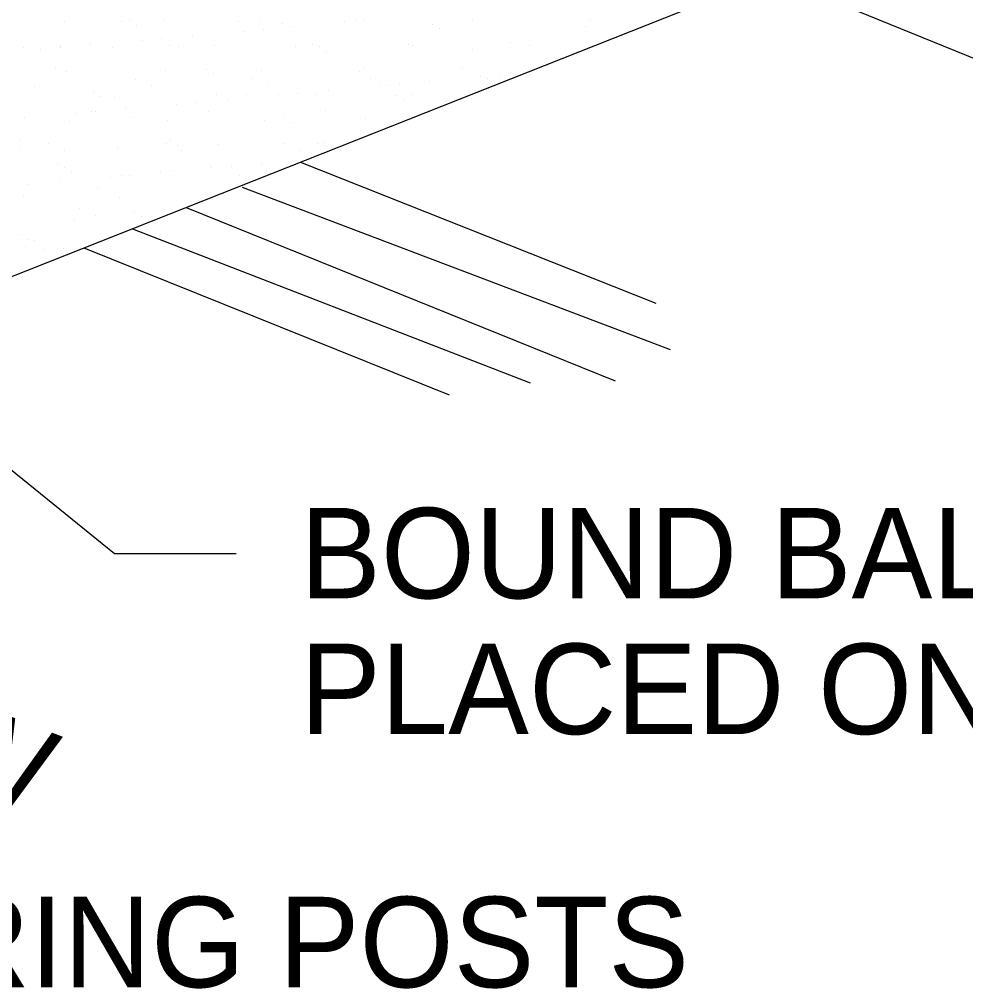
# Model space of a CAD drawing. Extents: x 636462 to 637367, y 299944 to 300538.
# Drawn here: x 636691.67 to 636723.01, y 300040.72 to 300072.82 of the extents above; entities that cross this region are included whole.
import ezdxf

# ---------------------------------------------------------------- set-up
doc = ezdxf.new("R2010")
doc.units = 0
doc.layers.add('Default', color=7, linetype='Continuous')

msp = doc.modelspace()

# ---------------------------------------------------------------- linework, layer by layer
at = {"layer": 'Default'}
for p, q in [((636625.772, 300111.279), (636734.467, 300066.973)), ((636653.687, 300049.343), (636731.791, 300080.316)), ((636693.164, 300072.747), (636693.164, 300072.747)), ((636695.034, 300072.762), (636695.034, 300072.762)), ((636695.307, 300072.775), (636695.307, 300072.775)), ((636695.537, 300072.63), (636695.537, 300072.63)), ((636696.428, 300072.775), (636696.428, 300072.775)), ((636698.917, 300072.767), (636698.917, 300072.767)), ((636699.618, 300072.765), (636699.618, 300072.765)), ((636700.37, 300072.699), (636700.37, 300072.699)), ((636702.445, 300072.74), (636702.445, 300072.74)), ((636702.801, 300072.771), (636702.801, 300072.771)), ((636703.094, 300072.799), (636703.094, 300072.799)), ((636705.361, 300072.669), (636705.361, 300072.669)), ((636706.684, 300072.776), (636706.684, 300072.776)), ((636710.568, 300072.781), (636710.568, 300072.781)), ((636697.394, 300072.284), (636697.394, 300072.284)), ((636699.088, 300072.437), (636699.088, 300072.437)), ((636699.737, 300072.496), (636699.737, 300072.496)), ((636700.751, 300072.587), (636700.751, 300072.587)), ((636705.59, 300072.525), (636705.59, 300072.525)), ((636710.424, 300072.594), (636710.424, 300072.594)), ((636694.037, 300071.98), (636694.037, 300071.98)), ((636695.731, 300072.133), (636695.731, 300072.133)), ((636696.38, 300072.192), (636696.38, 300072.192)), ((636698.114, 300071.972), (636698.114, 300071.972)), ((636701.379, 300072.001), (636701.379, 300072.001)), ((636704.569, 300071.99), (636704.569, 300071.99)), ((636707.937, 300072.074), (636707.937, 300072.074)), ((636691.788, 300071.878), (636691.788, 300071.878)), ((636692.374, 300071.83), (636692.374, 300071.83)), ((636693.024, 300071.888), (636693.024, 300071.888)), ((636693.043, 300071.929), (636693.043, 300071.929)), ((636694.746, 300071.889), (636694.746, 300071.889)), ((636696.622, 300071.947), (636696.622, 300071.947)), ((636696.927, 300071.933), (636696.927, 300071.933)), ((636700.81, 300071.938), (636700.81, 300071.938)), ((636701.612, 300071.918), (636701.612, 300071.918)), ((636701.842, 300071.773), (636701.842, 300071.773)), ((636704.694, 300071.943), (636704.694, 300071.943)), ((636706.675, 300071.842), (636706.675, 300071.842)), ((636708.577, 300071.948), (636708.577, 300071.948)), ((636692.873, 300071.195), (636692.873, 300071.195)), ((636693.242, 300071.096), (636693.242, 300071.096)), ((636696.507, 300071.125), (636696.507, 300071.125)), ((636697.863, 300071.166), (636697.863, 300071.166)), ((636698.093, 300071.021), (636698.093, 300071.021)), ((636699.697, 300071.114), (636699.697, 300071.114)), ((636702.926, 300071.09), (636702.926, 300071.09)), ((636703.065, 300071.198), (636703.065, 300071.198)), ((636706.329, 300071.226), (636706.329, 300071.226)), ((636707.917, 300071.061), (636707.917, 300071.061)), ((636695.515, 300070.847), (636695.515, 300070.847)), ((636699.398, 300070.852), (636699.398, 300070.852)), ((636703.282, 300070.857), (636703.282, 300070.857)), ((636704.244, 300070.685), (636704.244, 300070.685)), ((636705.258, 300070.777), (636705.258, 300070.777)), ((636706.952, 300070.93), (636706.952, 300070.93)), ((636707.166, 300070.861), (636707.166, 300070.861)), ((636707.601, 300070.989), (636707.601, 300070.989)), ((636692.157, 300070.612), (636692.157, 300070.612)), ((636694.114, 300070.414), (636694.114, 300070.414)), ((636696.041, 300070.617), (636696.041, 300070.617)), ((636699.924, 300070.622), (636699.924, 300070.622)), ((636700.887, 300070.382), (636700.887, 300070.382)), ((636701.901, 300070.473), (636701.901, 300070.473)), ((636703.595, 300070.627), (636703.595, 300070.627)), ((636703.808, 300070.627), (636703.808, 300070.627)), ((636694.344, 300070.269), (636694.344, 300070.269)), ((636694.825, 300070.238), (636694.825, 300070.238)), ((636697.53, 300070.078), (636697.53, 300070.078)), ((636698.193, 300070.322), (636698.193, 300070.322)), ((636698.544, 300070.17), (636698.544, 300070.17)), ((636699.178, 300070.338), (636699.178, 300070.338)), ((636700.238, 300070.323), (636700.238, 300070.323)), ((636701.457, 300070.35), (636701.457, 300070.35)), ((636704.168, 300070.309), (636704.168, 300070.309)), ((636704.398, 300070.164), (636704.398, 300070.164)), ((636704.647, 300070.34), (636704.647, 300070.34)), ((636693.524, 300069.716), (636693.524, 300069.716)), ((636694.05, 300069.784), (636694.05, 300069.784)), ((636694.173, 300069.775), (636694.173, 300069.775)), ((636695.187, 300069.866), (636695.187, 300069.866)), ((636696.881, 300070.02), (636696.881, 300070.02)), ((636697.934, 300069.788), (636697.934, 300069.788)), ((636701.818, 300069.793), (636701.818, 300069.793)), ((636691.83, 300069.563), (636691.83, 300069.563)), ((636693.321, 300069.446), (636693.321, 300069.446)), ((636695.429, 300069.586), (636695.429, 300069.586)), ((636696.585, 300069.474), (636696.585, 300069.474)), ((636699.775, 300069.464), (636699.775, 300069.464)), ((636700.419, 300069.557), (636700.419, 300069.557)), ((636700.649, 300069.412), (636700.649, 300069.412)), ((636703.144, 300069.547), (636703.144, 300069.547)), ((636691.68, 300068.835), (636691.68, 300068.835)), ((636696.67, 300068.805), (636696.67, 300068.805)), ((636691.713, 300068.598), (636691.713, 300068.598)), ((636692.638, 300068.697), (636692.638, 300068.697)), ((636693.164, 300068.467), (636693.164, 300068.467)), ((636694.903, 300068.588), (636694.903, 300068.588)), ((636696.522, 300068.702), (636696.522, 300068.702)), ((636696.9, 300068.66), (636696.9, 300068.66)), ((636697.048, 300068.472), (636697.048, 300068.472)), ((636698.272, 300068.671), (636698.272, 300068.671)), ((636700.406, 300068.707), (636700.406, 300068.707)), ((636700.931, 300068.477), (636700.931, 300068.477)), ((636701.536, 300068.7), (636701.536, 300068.7)), ((636701.734, 300068.729), (636701.734, 300068.729)), ((636692.921, 300068.053), (636692.921, 300068.053)), ((636693.151, 300067.909), (636693.151, 300067.909)), ((636693.399, 300067.795), (636693.399, 300067.795)), ((636696.664, 300067.824), (636696.664, 300067.824)), ((636697.985, 300067.978), (636697.985, 300067.978)), ((636698.031, 300067.906), (636698.031, 300067.906)), ((636698.68, 300067.964), (636698.68, 300067.964)), ((636699.694, 300068.056), (636699.694, 300068.056)), ((636699.854, 300067.813), (636699.854, 300067.813)), ((636700.973, 300068.095), (636712.741, 300063.42)), ((636694.674, 300067.602), (636694.674, 300067.602)), ((636695.058, 300067.639), (636695.058, 300067.639)), ((636695.323, 300067.661), (636695.323, 300067.661)), ((636696.337, 300067.752), (636696.337, 300067.752)), ((636698.941, 300067.643), (636698.941, 300067.643)), ((636691.966, 300067.357), (636691.966, 300067.357)), ((636692.98, 300067.449), (636692.98, 300067.449)), ((636694.236, 300067.226), (636694.236, 300067.226)), ((636699.048, 300067.27), (636713.221, 300061.886)), ((636691.792, 300066.948), (636691.792, 300066.948)), ((636694.982, 300066.937), (636694.982, 300066.937)), ((636693.646, 300066.552), (636693.646, 300066.552)), ((636697.193, 300066.596), (636711.393, 300060.853)), ((636694.172, 300066.322), (636694.172, 300066.322)), ((636695.477, 300066.445), (636695.477, 300066.445)), ((636695.707, 300066.3), (636695.707, 300066.3)), ((636693.478, 300066.145), (636693.478, 300066.145)), ((636695.413, 300065.89), (636708.588, 300060.789)), ((636691.728, 300065.693), (636691.728, 300065.693)), ((636691.958, 300065.548), (636691.958, 300065.548)), ((636691.87, 300065.297), (636691.87, 300065.297)), ((636692.181, 300065.489), (636692.181, 300065.489)), ((636693.116, 300065.243), (636693.116, 300065.243)), ((636693.801, 300065.251), (636705.902, 300060.385)), ((636692.467, 300065.185), (636692.467, 300065.185))]:
    msp.add_line(p, q, dxfattribs=at)
msp.add_lwpolyline([(636698.846, 300055.122), (636694.817, 300055.122), (636674.49, 300071.591)], dxfattribs=at)

# ---------------------------------------------------------------- texts
for s, p in [('BOUND BALES', (636700.963, 300053.645)), ('PLACED ON CONTOUR', (636700.963, 300049.147)), ('ANCHORING POSTS', (636674.642, 300040.76))]:
    msp.add_text(s, height=2.99804, dxfattribs=at).set_placement(p)
msp.add_text('FLOW', height=2.998, rotation=338.6988, dxfattribs=at).set_placement((636681.242, 300050.466))

doc.saveas('drawing.dxf')
